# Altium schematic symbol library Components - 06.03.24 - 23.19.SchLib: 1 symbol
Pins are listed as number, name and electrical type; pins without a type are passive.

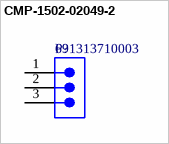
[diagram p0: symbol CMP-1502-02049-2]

## CMP-1502-02049-2
designator P?, comment 691313710003
NexarPartId: 18818335; Connector Type: PCB, Terminal Block; Current Rating: 20A; Number of Contacts: 3; Voltage: 300V; Pitch: 5.0038mm; Gender: Male; Number of Levels: 1
footprint PCBComponent_1
pins: 1, 2, 3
